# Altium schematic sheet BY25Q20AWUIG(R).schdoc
size 127 x 101 mm
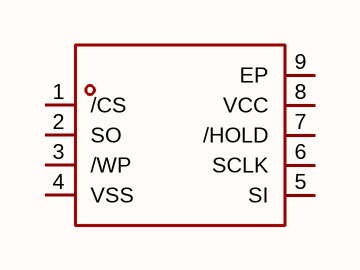
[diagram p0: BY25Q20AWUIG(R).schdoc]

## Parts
U?  by25q20awuig(r)  [USON-8_L3.0-W2.0-P0.50-BL-EP]  (value not drawn)

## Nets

Not connected (* = marked no-connect by the designer): U? 1(/CS) 2(SO) 3(/WP) 4(VSS) 5(SI) 6(SCLK) 7(/HOLD) 8(VCC) 9(EP)

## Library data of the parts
U? = by25q20awuig(r): 接口类型:SPI;存储容量:2Mbit;时钟频率(fc):85MHz;; Manufacturer: BOYAMICRO(博雅); AddInBom: yes; ModelId: 2b35e1c3dcc44b77887d4f445b51370a; ModelName: USON-8_L2-W3-H0.6X0.5P; ModelTransform: 79.527,118.8974,0,0,0,0,-0.313,-1.1,0; Interface: SPI; Memory Size: 2Mbit; Clock Frequency: 85MHz; Voltage - Supply: 1.65V~3.6V; Standby Supply Current: 0.6uA; Program / Erase Cycles: 100000次; Page Programming Time (Tpp): 2ms; Block Erase Time(tBE): 8ms; Data Retention - TDR (Year): 20年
